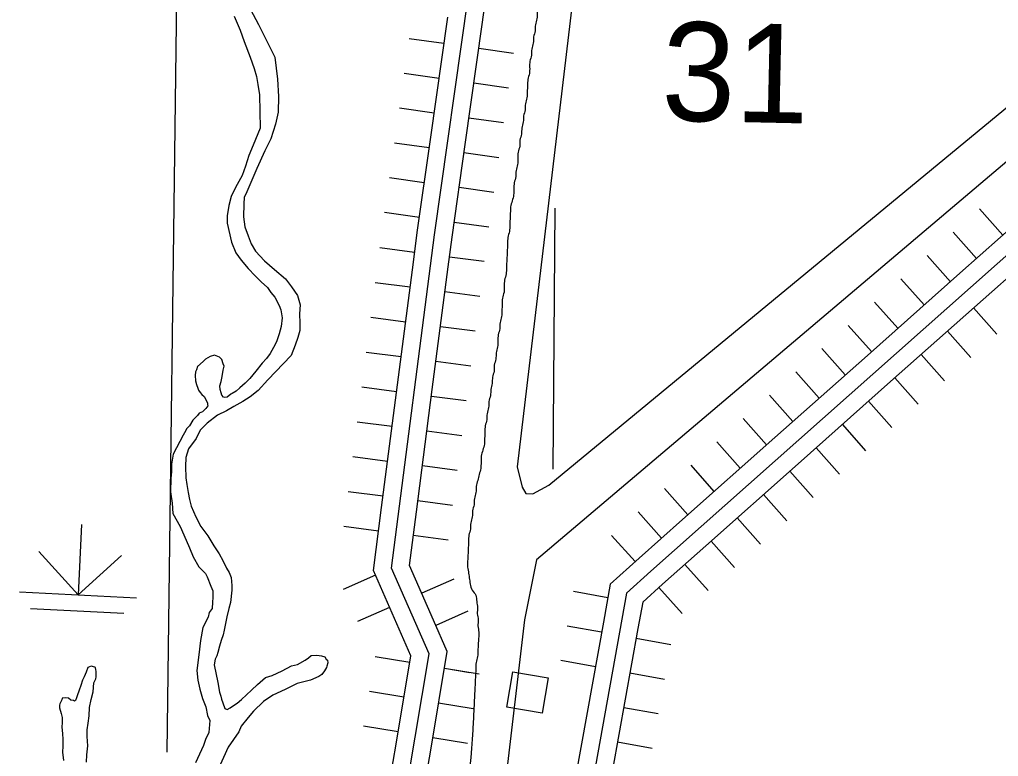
# Model space of a CAD drawing. Extents: x -4306 to 3843, y 131 to 8053.
# Drawn here: x -2773 to -2104, y 5427 to 5931 of the extents above; entities that cross this region are included whole.
import ezdxf

# ---------------------------------------------------------------- set-up
doc = ezdxf.new("R2010")
doc.units = 0
for name, color, linetype in [('29', 7, 'Continuous'), ('32', 7, 'Continuous'), ('35', 7, 'Continuous'), ('4', 7, 'Continuous'), ('43', 7, 'Continuous'), ('44', 7, 'Continuous'), ('5', 7, 'Continuous'), ('57', 7, 'Continuous'), ('7', 7, 'Continuous')]:
    doc.layers.add(name, color=color, linetype=linetype)

msp = doc.modelspace()

# ---------------------------------------------------------------- linework, layer by layer
at = {"layer": '29'}
for p, q in [((-2483.31, 5914.13), (-2507.07, 5917.49)), ((-2483.31, 5914.13), (-2507.07, 5917.49)), ((-2435.78, 5907.4), (-2459.54, 5910.76)), ((-2435.78, 5907.4), (-2459.54, 5910.76)), ((-2486.67, 5890.36), (-2510.44, 5893.72)), ((-2439.14, 5883.63), (-2462.91, 5887)), ((-2490.04, 5866.59), (-2513.8, 5869.96)), ((-2442.51, 5859.87), (-2466.27, 5863.23)), ((-2493.4, 5842.83), (-2517.17, 5846.19)), ((-2493.4, 5842.83), (-2517.17, 5846.19)), ((-2445.87, 5836.1), (-2469.64, 5839.46)), ((-2445.87, 5836.1), (-2469.64, 5839.46)), ((-2496.77, 5819.06), (-2520.53, 5822.43)), ((-2449.23, 5812.33), (-2473, 5815.7)), ((-2500.13, 5795.3), (-2523.9, 5798.66)), ((-2117.11, 5801.24), (-2101.18, 5783.28)), ((-2452.6, 5788.57), (-2476.36, 5791.93)), ((-2135.07, 5785.3), (-2119.14, 5767.35)), ((-2135.07, 5785.3), (-2119.14, 5767.35)), ((-2503.36, 5771.37), (-2527.16, 5774.46)), ((-2503.36, 5771.37), (-2527.16, 5774.46)), ((-2153.02, 5769.37), (-2137.09, 5751.42)), ((-2455.75, 5765.2), (-2479.55, 5768.28)), ((-2455.75, 5765.2), (-2479.55, 5768.28)), ((-2506.44, 5747.57), (-2530.25, 5750.66)), ((-2170.97, 5753.44), (-2155.04, 5735.49)), ((-2458.84, 5741.39), (-2482.64, 5744.48)), ((-2188.93, 5737.51), (-2173, 5719.56)), ((-2188.93, 5737.51), (-2173, 5719.56)), ((-2121.16, 5733.47), (-2105.23, 5715.51)), ((-2509.53, 5723.77), (-2533.34, 5726.85)), ((-2461.93, 5717.59), (-2485.73, 5720.68)), ((-2206.88, 5721.58), (-2190.95, 5703.63)), ((-2139.11, 5717.54), (-2123.18, 5699.58)), ((-2512.62, 5699.96), (-2536.42, 5703.05)), ((-2512.62, 5699.96), (-2536.42, 5703.05)), ((-2224.84, 5705.65), (-2208.91, 5687.7)), ((-2465.02, 5693.79), (-2488.82, 5696.87)), ((-2465.02, 5693.79), (-2488.82, 5696.87)), ((-2157.07, 5701.61), (-2141.14, 5683.65)), ((-2157.07, 5701.61), (-2141.14, 5683.65)), ((-2242.79, 5689.72), (-2226.86, 5671.77)), ((-2242.79, 5689.72), (-2226.86, 5671.77)), ((-2175.02, 5685.68), (-2159.09, 5667.72)), ((-2515.71, 5676.16), (-2539.51, 5679.25)), ((-2468.1, 5669.98), (-2491.91, 5673.07)), ((-2260.75, 5673.79), (-2244.82, 5655.84)), ((-2192.98, 5669.75), (-2177.05, 5651.79)), ((-2518.8, 5652.36), (-2542.6, 5655.45)), ((-2278.7, 5657.86), (-2262.77, 5639.91)), ((-2471.19, 5646.18), (-2495, 5649.27)), ((-2210.93, 5653.82), (-2195, 5635.86)), ((-2210.93, 5653.82), (-2195, 5635.86)), ((-2296.65, 5641.93), (-2280.72, 5623.98)), ((-2296.65, 5641.93), (-2280.72, 5623.98)), ((-2228.89, 5637.89), (-2212.96, 5619.93)), ((-2521.89, 5628.55), (-2545.69, 5631.64)), ((-2521.89, 5628.55), (-2545.69, 5631.64)), ((-2474.28, 5622.38), (-2498.08, 5625.47)), ((-2474.28, 5622.38), (-2498.08, 5625.47)), ((-2314.61, 5626), (-2298.68, 5608.05)), ((-2246.84, 5621.96), (-2230.91, 5604)), ((-2332.56, 5610.07), (-2316.63, 5592.12)), ((-2524.98, 5604.75), (-2548.78, 5607.84)), ((-2477.37, 5598.57), (-2501.17, 5601.66)), ((-2264.79, 5606.03), (-2248.86, 5588.07)), ((-2264.79, 5606.03), (-2248.86, 5588.07)), ((-2350.52, 5594.14), (-2334.59, 5576.19)), ((-2350.52, 5594.14), (-2334.59, 5576.19)), ((-2282.75, 5590.1), (-2266.82, 5572.14)), ((-2528.06, 5580.95), (-2551.87, 5584.04)), ((-2480.46, 5574.77), (-2504.26, 5577.86)), ((-2368.74, 5577.92), (-2352.61, 5560.14)), ((-2300.7, 5574.17), (-2284.77, 5556.21)), ((-2318.66, 5558.24), (-2302.73, 5540.28)), ((-2318.66, 5558.24), (-2302.73, 5540.28)), ((-2530.16, 5550.78), (-2552.13, 5541.1)), ((-2530.16, 5550.78), (-2552.13, 5541.1)), ((-2476.56, 5548.15), (-2498.52, 5538.48)), ((-2336.49, 5542.36), (-2320.36, 5524.58)), ((-2394.85, 5539.91), (-2371.23, 5535.65)), ((-2520.49, 5528.81), (-2542.46, 5519.14)), ((-2466.88, 5526.18), (-2488.85, 5516.51)), ((-2399.11, 5516.29), (-2375.49, 5512.03)), ((-2399.11, 5516.29), (-2375.49, 5512.03)), ((-2351.87, 5507.76), (-2328.25, 5503.5)), ((-2351.87, 5507.76), (-2328.25, 5503.5)), ((-2506.65, 5491.12), (-2530.31, 5495.11)), ((-2506.65, 5491.12), (-2530.31, 5495.11)), ((-2403.38, 5492.67), (-2379.76, 5488.4)), ((-2459.31, 5483.15), (-2482.98, 5487.14)), ((-2465.62, 5484.22), (-2482.98, 5487.14)), ((-2356.14, 5484.14), (-2332.51, 5479.88)), ((-2510.63, 5467.45), (-2534.3, 5471.44)), ((-2463.29, 5459.48), (-2486.96, 5463.47)), ((-2360.4, 5460.52), (-2336.78, 5456.26)), ((-2514.61, 5443.78), (-2538.28, 5447.77)), ((-2467.28, 5435.81), (-2490.94, 5439.8)), ((-2364.66, 5436.9), (-2341.04, 5432.64)), ((-2364.66, 5436.9), (-2341.04, 5432.64))]:
    msp.add_line(p, q, dxfattribs=at)
at = {"layer": '32'}
for p, q in [((-2489.69, 5783.46), (-2455.31, 6026.29)), ((-2489.69, 5783.46), (-2455.31, 6026.29)), ((-2456.98, 5928.82), (-2445.14, 6012.48)), ((-2492.59, 5848.53), (-2480.75, 5932.19)), ((-2468.83, 5845.17), (-2456.98, 5928.82)), ((-2501.58, 5785.07), (-2492.59, 5848.53)), ((-2477.79, 5781.84), (-2468.83, 5845.17)), ((-2011.81, 5846.53), (-2341.92, 5553.64)), ((-2011.81, 5846.53), (-2341.92, 5553.64)), ((-2067.43, 5813.23), (-2130.63, 5757.16)), ((-2051.5, 5795.27), (-2114.7, 5739.2)), ((-2519.23, 5555.73), (-2489.69, 5783.46)), ((-2519.23, 5555.73), (-2489.69, 5783.46)), ((-2504.22, 5764.71), (-2501.58, 5785.07)), ((-2480.42, 5761.62), (-2477.79, 5781.84)), ((-2515.09, 5680.92), (-2504.22, 5764.71)), ((-2491.29, 5677.83), (-2480.42, 5761.62)), ((-2130.63, 5757.16), (-2193.83, 5701.08)), ((-2114.7, 5739.2), (-2177.9, 5683.13)), ((-2193.83, 5701.08), (-2257.03, 5645.01)), ((-2177.9, 5683.13), (-2241.09, 5627.05)), ((-2525.96, 5597.13), (-2515.09, 5680.92)), ((-2502.16, 5594.05), (-2491.29, 5677.83)), ((-2257.03, 5645.01), (-2320.22, 5588.93)), ((-2241.09, 5627.05), (-2304.29, 5570.98)), ((-2531.57, 5553.96), (-2525.96, 5597.13)), ((-2506.9, 5557.51), (-2502.16, 5594.05)), ((-2320.22, 5588.93), (-2349.93, 5562.57)), ((-2304.29, 5570.98), (-2333.91, 5544.71)), ((-2349.93, 5562.57), (-2369.59, 5544.75)), ((-2493.45, 5497.18), (-2519.23, 5555.73)), ((-2493.45, 5497.18), (-2519.23, 5555.73)), ((-2490.4, 5520.03), (-2506.9, 5557.51)), ((-2512.37, 5510.35), (-2531.57, 5553.96)), ((-2341.92, 5553.64), (-2358.5, 5538.6)), ((-2341.92, 5553.64), (-2358.5, 5538.6)), ((-2369.59, 5544.75), (-2374.3, 5518.64)), ((-2333.91, 5544.71), (-2347.42, 5532.45)), ((-2358.5, 5538.6), (-2381.79, 5409.56)), ((-2358.5, 5538.6), (-2381.79, 5409.56)), ((-2347.42, 5532.45), (-2350.68, 5514.38)), ((-2481.02, 5498.73), (-2490.4, 5520.03)), ((-2374.3, 5518.64), (-2389.31, 5435.49)), ((-2505.89, 5495.63), (-2512.37, 5510.35)), ((-2350.68, 5514.38), (-2368.11, 5417.77)), ((-2529.5, 5283.08), (-2493.45, 5497.18)), ((-2529.5, 5283.08), (-2493.45, 5497.18)), ((-2516.05, 5435.26), (-2505.89, 5495.63)), ((-2492.38, 5431.28), (-2481.02, 5498.73)), ((-2530.07, 5351.94), (-2516.05, 5435.26)), ((-2389.31, 5435.49), (-2393.62, 5411.59)), ((-2506.41, 5347.96), (-2492.38, 5431.28))]:
    msp.add_line(p, q, dxfattribs=at)
at = {"layer": '35'}
for points in [[(-2618.93, 5943.74), (-2610.16, 5927.26), (-2598.9, 5904.96), (-2597.15, 5889.84), (-2596.33, 5877.95), (-2596.77, 5867.36), (-2598.46, 5859.03), (-2601.77, 5849.12), (-2605.7, 5840.82), (-2611.27, 5828.69), (-2614.56, 5820.7), (-2618.17, 5812.72), (-2619.81, 5808.88), (-2620.18, 5804.71), (-2620.28, 5795.72), (-2619.4, 5788.97), (-2617.23, 5782.84), (-2615.05, 5777.35), (-2612.23, 5772.18), (-2605.91, 5765.68), (-2599.26, 5759.82), (-2591.65, 5753.3), (-2587.56, 5747.79), (-2583.47, 5741.96), (-2581.62, 5735.51), (-2582.01, 5729.42), (-2581.76, 5722.99), (-2581.82, 5718.17), (-2583.15, 5713.37), (-2585.13, 5707.94), (-2587.77, 5700.91), (-2603.62, 5684.41), (-2610.42, 5677.11), (-2615.91, 5672.68), (-2620.74, 5669.53), (-2626.86, 5666.08), (-2632.01, 5663.25), (-2638.12, 5660.11), (-2645.21, 5654.74), (-2650.06, 5649.99), (-2652.69, 5644.24), (-2657.88, 5637.24), (-2659.87, 5631.17), (-2659.94, 5625.07), (-2659.71, 5617.36), (-2659.12, 5612.85), (-2658.22, 5607.38)], [(-2626.73, 5932.92), (-2622.68, 5923.24), (-2619.89, 5915.5), (-2615.85, 5904.85), (-2613.06, 5897.11), (-2611.52, 5891.63), (-2610.63, 5886.16), (-2609.43, 5879.08), (-2609.04, 5856.27), (-2613.65, 5844.77), (-2616.61, 5837.74), (-2618.93, 5830.39), (-2621.24, 5823.99), (-2625.81, 5815.7), (-2628.76, 5809.64), (-2630.43, 5803.56), (-2631.46, 5796.51), (-2631.52, 5791.37), (-2628.47, 5778.49), (-2625.67, 5771.07), (-2621.89, 5766.2), (-2617.16, 5760.36), (-2612.42, 5755.49), (-2608.31, 5751.26), (-2603.87, 5747.35), (-2601.67, 5744.11)], [(-2601.67, 5744.11), (-2598.83, 5740.87), (-2596.02, 5735.05), (-2594.77, 5732.14), (-2593.87, 5726.67), (-2594.58, 5720.9), (-2595.91, 5715.78), (-2597.89, 5710.35), (-2599.86, 5706.52), (-2602.14, 5702.37), (-2604.74, 5698.87), (-2607.65, 5695.7), (-2611.87, 5690.29), (-2616.09, 5685.21), (-2619.32, 5682.04), (-2622.87, 5678.87), (-2625.46, 5676.65), (-2628.03, 5675.08), (-2629, 5674.45), (-2631.58, 5672.56), (-2633.18, 5672.26), (-2634.14, 5672.59), (-2635.08, 5673.88), (-2635.7, 5675.5), (-2636.32, 5677.75), (-2636.61, 5680.33), (-2635.62, 5683.2), (-2634.94, 5686.73), (-2634.25, 5690.89), (-2633.58, 5693.78), (-2634.2, 5695.39), (-2635.13, 5698.29), (-2636.71, 5699.92), (-2640.21, 5701.24), (-2643.1, 5700.32), (-2646.32, 5698.43), (-2647.94, 5696.85), (-2651.81, 5693.36), (-2652.48, 5691.12), (-2653.13, 5689.85), (-2653.48, 5687.28), (-2653.2, 5683.75), (-2652.59, 5681.17), (-2651.66, 5678.59), (-2651.04, 5677.3), (-2650.09, 5675.68), (-2648.83, 5674.38), (-2647.25, 5673.07), (-2646.3, 5671.46), (-2646, 5670.17), (-2645.06, 5668.55), (-2645.07, 5667.59), (-2644.76, 5666.62), (-2646.06, 5664.71), (-2648.32, 5662.49), (-2650.57, 5661.56), (-2651.87, 5659.97), (-2655.1, 5656.8), (-2657.39, 5652.97), (-2659.01, 5651.06), (-2660.64, 5648.19), (-2661.62, 5646.6), (-2663.9, 5642.13), (-2668.48, 5633.52), (-2669.51, 5626.79), (-2669.57, 5621.65), (-2669.95, 5616.84), (-2670.37, 5607.86), (-2669.17, 5600.13), (-2668.61, 5593.06), (-2663.6, 5584.01), (-2661.1, 5578.52), (-2657.37, 5569.48), (-2654.88, 5563.35), (-2650.8, 5556.55), (-2646.37, 5552), (-2645.12, 5549.74), (-2642.63, 5543.28), (-2641.39, 5540.06), (-2641.44, 5535.56), (-2641.47, 5532.35), (-2641.84, 5528.18), (-2643.79, 5525.32), (-2644.47, 5522.11), (-2648.07, 5515.09), (-2649.77, 5506.12), (-2650.83, 5496.5), (-2652.23, 5485.6), (-2651.67, 5479.17), (-2650.14, 5473.05), (-2648.29, 5466.61), (-2646.12, 5460.8), (-2644.9, 5455.01), (-2643.34, 5451.45), (-2643.73, 5446), (-2644.07, 5443.44), (-2646.37, 5438.65), (-2647.69, 5434.49), (-2653.26, 5422.68)], [(-2658.22, 5607.38), (-2657.31, 5602.55), (-2656.09, 5598.04), (-2652.97, 5590.62), (-2649.53, 5584.15), (-2644.8, 5577.67), (-2640.72, 5570.88), (-2636.95, 5565.37), (-2634.44, 5560.84), (-2631.94, 5555.67), (-2630.05, 5552.76), (-2628.81, 5549.21), (-2628.23, 5543.75), (-2628.27, 5540.54), (-2629.32, 5532.2), (-2630.33, 5528.04), (-2631.67, 5522.28), (-2632.68, 5517.79), (-2633.69, 5513.31), (-2634.37, 5510.11), (-2635.69, 5506.27), (-2636.69, 5502.43), (-2638.02, 5497.95), (-2638.69, 5495.71), (-2639.67, 5493.47), (-2640.36, 5489.63), (-2637.94, 5477.4), (-2636.73, 5470.96), (-2635.8, 5468.06), (-2635.5, 5466.13), (-2634.57, 5463.55), (-2633.02, 5459.67), (-2631.43, 5459.01), (-2629.49, 5460.27), (-2626.59, 5462.16), (-2624.66, 5463.42), (-2621.75, 5465.96), (-2614.97, 5472.29), (-2610.77, 5476.09), (-2605.28, 5480.84), (-2600.78, 5482.39), (-2594.03, 5485.52), (-2587.59, 5488.97), (-2583.43, 5489.88), (-2578.28, 5492.71), (-2576.02, 5494.28), (-2574.08, 5495.86), (-2570.24, 5496.14), (-2567.05, 5495.78), (-2564.82, 5495.11), (-2563.88, 5493.49), (-2562.93, 5492.83), (-2562.63, 5490.9), (-2563.29, 5488.66), (-2563.62, 5487.71), (-2564.93, 5485.47), (-2566.87, 5482.93), (-2568.81, 5481.67), (-2574.59, 5479.17), (-2583.57, 5476.72), (-2591.94, 5472.65), (-2600.29, 5468.9), (-2606.74, 5464.48), (-2613.53, 5457.82), (-2617.09, 5453.69), (-2621.96, 5447.65), (-2623.6, 5443.82), (-2630.76, 5433.31), (-2637.31, 5419.27)], [(-2727.78, 5422.97), (-2727.4, 5428.1), (-2726.69, 5434.19), (-2727.26, 5440.62), (-2727.21, 5445.12), (-2726.52, 5449.61), (-2725.82, 5454.74), (-2725.76, 5460.51), (-2724.41, 5465.96), (-2723.08, 5471.08), (-2722.69, 5477.17), (-2721.38, 5480.05), (-2721.04, 5481.33), (-2721.01, 5484.54), (-2721, 5485.18), (-2721.31, 5486.15), (-2721.61, 5487.76), (-2721.93, 5488.08), (-2724.48, 5488.76), (-2726.73, 5487.82), (-2728.04, 5484.63), (-2729.36, 5481.43), (-2730.34, 5479.2), (-2731.66, 5475.36), (-2732.66, 5472.16), (-2733.98, 5468.32), (-2734.64, 5467.05), (-2735.3, 5465.13), (-2735.94, 5464.82), (-2736.58, 5465.15), (-2738.49, 5465.49), (-2740.08, 5466.8), (-2742.31, 5467.14), (-2744.23, 5466.85), (-2744.57, 5465.57), (-2745.88, 5463.01), (-2746.21, 5462.06), (-2746.23, 5460.13), (-2744.99, 5456.26), (-2744.38, 5453.68), (-2744.42, 5450.15), (-2744.46, 5446.94), (-2744.18, 5442.76), (-2743.91, 5438.58), (-2743.96, 5434.09), (-2744.01, 5429.92), (-2743.43, 5424.13)]]:
    msp.add_lwpolyline(points, dxfattribs=at)
at = {"layer": '4'}
msp.add_line((-2672.44, 5429.89), (-2664.73, 6032.85), dxfattribs=at)
at = {"layer": '43'}
for points in [[(-2398.45, 6031.65), (-2398.26, 6036.99), (-2394.95, 6040.1), (-2389.74, 6035.36), (-2388.72, 6026.47), (-2387.16, 6010.6), (-2387.62, 6008.6), (-2433.19, 5624.79), (-2429.83, 5610.94), (-2427.32, 5606.74), (-2422.53, 5606.36), (-2411.59, 5612.32), (-2032.72, 5924.64)], [(-2017.93, 5901.63), (-2419.98, 5561.32)], [(-2419.98, 5561.32), (-2428.14, 5520.43), (-2455.18, 5291.97), (-2489.16, 5041.29), (-2521.81, 4920.48), (-2538.06, 4862.99), (-2570.96, 4832.09), (-2659.53, 4768.87)]]:
    msp.add_lwpolyline(points, dxfattribs=at)
for points in [[(-2398.45, 6031.65), (-2399.02, 6030.37), (-2400.06, 6026.24), (-2402.72, 6023.03), (-2404.59, 6018.94), (-2406.46, 6014.86), (-2407.5, 6010.73), (-2406.51, 6014.02), (-2407.54, 6009.9), (-2408.58, 6005.77), (-2408.78, 6001.6), (-2409.82, 5997.48), (-2410.02, 5993.31), (-2410.23, 5989.14), (-2411.27, 5985.01), (-2411.47, 5980.84), (-2412.51, 5976.72), (-2413.54, 5972.59), (-2414.58, 5968.46), (-2415.62, 5964.34), (-2415.82, 5960.17), (-2416.86, 5956.04), (-2417.06, 5951.87), (-2417.27, 5947.71), (-2418.3, 5943.58), (-2418.51, 5939.41), (-2419.55, 5935.28), (-2419.75, 5931.12), (-2420.79, 5926.99), (-2420.99, 5922.82), (-2422.03, 5918.69), (-2422.23, 5914.53), (-2423.27, 5910.4), (-2423.47, 5906.23), (-2424.51, 5902.1), (-2424.71, 5897.94), (-2424.92, 5893.77), (-2425.95, 5889.64), (-2426.16, 5885.47), (-2426.36, 5881.3), (-2426.57, 5877.14), (-2427.6, 5873.01), (-2427.81, 5868.84), (-2428.84, 5864.71), (-2429.05, 5860.55), (-2430.08, 5856.42), (-2430.29, 5852.25), (-2431.33, 5848.13), (-2431.53, 5843.96), (-2432.57, 5839.83), (-2432.77, 5835.66), (-2432.97, 5831.49), (-2434.01, 5827.37), (-2434.22, 5823.2), (-2435.25, 5819.07), (-2435.46, 5814.9), (-2435.66, 5810.74), (-2436.7, 5806.61), (-2437.73, 5802.48), (-2437.94, 5798.31), (-2438.14, 5794.15), (-2438.35, 5789.98), (-2438.55, 5785.81), (-2439.59, 5781.68), (-2439.79, 5777.52), (-2439.99, 5773.35), (-2440.2, 5769.18), (-2440.4, 5765.01), (-2440.61, 5760.84), (-2440.81, 5756.68), (-2441.85, 5752.55), (-2442.05, 5748.38), (-2442.25, 5744.21), (-2443.29, 5740.09), (-2443.5, 5735.92), (-2443.7, 5731.75), (-2443.9, 5727.58), (-2444.94, 5723.46), (-2445.14, 5719.29), (-2446.18, 5715.16), (-2446.39, 5710.99), (-2446.59, 5706.83), (-2447.63, 5702.7), (-2447.83, 5698.53), (-2448.87, 5694.4), (-2449.07, 5690.24), (-2450.11, 5686.11), (-2450.31, 5681.94), (-2451.35, 5677.81)], [(-2451.35, 5677.81), (-2451.55, 5673.65), (-2452.59, 5669.52), (-2452.79, 5665.35), (-2453.83, 5661.22), (-2454.03, 5657.06), (-2455.07, 5652.93), (-2455.28, 5648.76), (-2455.48, 5644.59), (-2455.68, 5640.42), (-2456.72, 5636.3), (-2457.76, 5632.17), (-2457.96, 5628), (-2458.17, 5623.83), (-2459.2, 5619.71), (-2460.24, 5615.58), (-2461.28, 5611.45), (-2461.48, 5607.29), (-2462.52, 5603.16), (-2462.72, 5598.99), (-2463.76, 5594.86), (-2463.96, 5590.7), (-2465, 5586.57), (-2465.2, 5582.4), (-2466.24, 5578.27), (-2466.44, 5574.11), (-2466.65, 5569.94), (-2466.85, 5565.77), (-2467.06, 5561.6), (-2467.26, 5557.43), (-2466.63, 5553.23), (-2466, 5549.02), (-2465.37, 5544.81), (-2463.91, 5540.56), (-2461.57, 5537.1), (-2460.94, 5532.89), (-2460.31, 5528.69), (-2460.52, 5524.52), (-2459.89, 5520.31), (-2460.09, 5516.14), (-2459.46, 5511.93), (-2459.66, 5507.76), (-2459.87, 5503.6), (-2460.07, 5499.43), (-2460.28, 5495.26), (-2461.31, 5491.13), (-2461.52, 5486.97), (-2461.72, 5482.8), (-2461.92, 5478.63), (-2462.13, 5474.46), (-2462.33, 5470.29), (-2462.45, 5467.79), (-2462.66, 5463.63), (-2462.86, 5459.46), (-2463.07, 5455.29), (-2463.27, 5451.12), (-2495.25, 5254.04)]]:
    msp.add_spline(points, degree=3, dxfattribs=at)
at = {"layer": '44'}
for p, q in [((-2731.16, 5585.38), (-2733.5, 5537.43)), ((-2733.5, 5537.43), (-2760.38, 5567.07)), ((-2733.5, 5537.43), (-2703.87, 5564.31)), ((-2773.46, 5539.39), (-2693.55, 5535.48)), ((-2766, 5528.1), (-2702.07, 5524.98))]:
    msp.add_line(p, q, dxfattribs=at)
at = {"layer": '57'}
msp.add_lwpolyline([(-2416.12, 5456.64), (-2440.27, 5460.68), (-2436.23, 5484.83), (-2412.08, 5480.79)], close=True, dxfattribs=at)
at = {"layer": '7'}
msp.add_line((-2407.42, 5801.55), (-2408.93, 5623.21), dxfattribs=at)

# ---------------------------------------------------------------- texts
at = {"layer": '5'}
msp.add_text('31', height=67.591, rotation=358.75468, dxfattribs=at).set_placement((-2334.96, 5861.69))

doc.saveas('drawing.dxf')
